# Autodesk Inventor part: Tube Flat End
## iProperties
Shininess: 20.0
Angle Display Precision: 2
Document Length Units: 11269
Document Angle Units: 11279
Document Time Units: 11290
Document Mass Units: 11283
Document Length Units Precision: 3
Document Angle Units Precision: 2
Compacted: True
Created: 2001-08
Part Number: Tube Flat End
Document SubType Name: Modeling
Designer: Martin Budgell
Density: 0.0
Volumn: 0.0
Area: 0.0
PropertySet Name: Model Information
Control State: 0
Master: False
Checked Out: False
Author: Martin Budgell
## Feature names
1. Loft1
2. Extrusion1
3. Extrusion2
4. Loft3
5. Extrusion3
6. Extrusion4
7. Extrusion5
8. Extrusion6
9. Chamfer1
